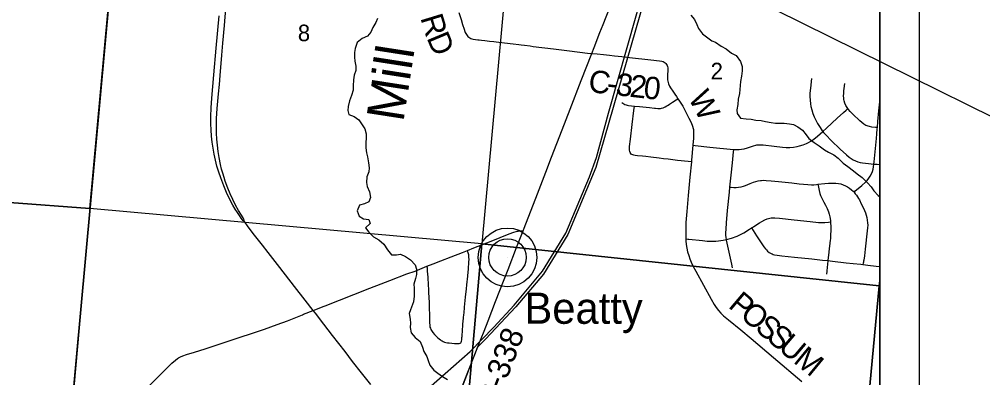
# Model space of a CAD drawing. Extents: x 0 to 34, y 0 to 22.
# Drawn here: x 6.722 to 9.161, y 14.717 to 15.624 of the extents above; entities that cross this region are included whole.
import ezdxf

# ---------------------------------------------------------------- set-up
doc = ezdxf.new("R2010")
doc.units = 0
for name, color, linetype in [('Default', 7, 'Continuous'), ('GM_X_City_Street', 7, 'Continuous'), ('GM_X_County_Road', 7, 'Continuous'), ('GM_X_County_Road_Text', 7, 'Continuous'), ('GM_X_Minor_River', 7, 'Continuous'), ('GM_X_Minor_River_Text', 7, 'Continuous'), ('GM_X_Rail_Line', 7, 'Continuous'), ('GM_X_Section', 7, 'Continuous'), ('GM_X_Section_Text', 7, 'Continuous'), ('GM_X_Township_Road', 7, 'Continuous'), ('GM_X_Township_Road_Text', 7, 'Continuous'), ('GM_X_Unincorporated', 7, 'Continuous'), ('GM_X_Unincorporated_Location', 7, 'Continuous'), ('GM_X_Unincorporated_Text', 7, 'Continuous'), ('GM_X_US_Route', 7, 'Continuous'), ('SH_Data', 7, 'Continuous'), ('SH_Text', 7, 'Continuous')]:
    doc.layers.add(name, color=color, linetype=linetype)

msp = doc.modelspace()

# ---------------------------------------------------------------- linework, layer by layer
at = {"layer": 'Default'}
for points in [[(8.9, 14.9629), (8.9, 15.9657), (7.9848, 16.0585), (7.893, 15.0559), (8.8988, 14.9496)], [(7.2235, 14.1), (7.8093, 14.1), (7.893, 15.0559), (6.9002, 15.1449), (6.8099, 14.1356), (6.8432, 14.1321)], [(7.8093, 14.1), (8.8187, 14.1), (8.8988, 14.9496), (7.893, 15.0559)], [(8.9, 14.9495), (8.9, 14.9629), (8.8988, 14.9496)], [(8.8187, 14.1), (8.9, 14.1), (8.9, 14.9495), (8.8988, 14.9496)]]:
    msp.add_lwpolyline(points, close=True, dxfattribs=at)
at = {"layer": 'GM_X_City_Street'}
for points in [[(8.9, 14.1), (8.9, 20.0308)], [(6.6663, 17.4414), (6.7406, 17.4254), (6.8171, 17.414), (6.8537, 17.4026), (6.8949, 17.4037), (6.9475, 17.3946), (6.9749, 17.3832), (6.9943, 17.3798), (7.048, 17.3741), (7.0629, 17.3706), (7.1058, 17.3541), (7.096, 17.2767), (7.0907, 17.2272), (7.0417, 16.6723), (7.0099, 16.337), (6.9769, 15.9806), (6.9764, 15.9754), (6.9745, 15.9547), (6.9742, 15.9512), (6.8413, 14.4929)], [(6.8413, 14.4929), (6.9742, 15.9512), (6.9745, 15.9547), (6.9764, 15.9754), (6.9769, 15.9806), (7.0099, 16.337), (7.0417, 16.6723), (7.0907, 17.2272), (7.096, 17.2767), (7.1058, 17.3541), (7.0629, 17.3706), (7.048, 17.3741), (6.9943, 17.3798), (6.9749, 17.3832), (6.9475, 17.3946), (6.8949, 17.4037), (6.8537, 17.4026), (6.8171, 17.414), (6.7406, 17.4254), (6.6663, 17.4414)]]:
    msp.add_lwpolyline(points, dxfattribs=at)
at = {"layer": 'GM_X_County_Road'}
msp.add_line((7.4657, 14.887), (7.4936, 14.8979), dxfattribs=at)
for points in [[(8.1707, 15.5377), (8.1766, 15.553), (8.1914, 15.5905), (8.1994, 15.6107), (8.217, 15.6538), (8.246, 15.7225), (8.2645, 15.7652), (8.2816, 15.8055)], [(7.997, 15.0885), (7.9997, 15.0955), (8.0333, 15.1823), (8.0546, 15.2374), (8.0691, 15.275), (8.0827, 15.3097), (8.096, 15.3445), (8.1163, 15.3965), (8.1444, 15.4689), (8.1707, 15.5377)], [(8.1707, 15.5377), (8.1845, 15.5364), (8.2007, 15.5346), (8.2081, 15.5338), (8.2157, 15.533), (8.2281, 15.5317), (8.2466, 15.5297), (8.2665, 15.5275), (8.3206, 15.5213), (8.3425, 15.5188), (8.3485, 15.5178), (8.3514, 15.517), (8.3541, 15.5158), (8.3565, 15.5142), (8.3587, 15.5122), (8.3604, 15.5098), (8.3618, 15.5072), (8.3627, 15.5044), (8.3632, 15.5014), (8.3633, 15.4984), (8.3632, 15.4923), (8.3629, 15.4861), (8.3625, 15.4768), (8.3627, 15.4705), (8.3631, 15.4673), (8.3639, 15.4639), (8.3651, 15.4605), (8.3678, 15.4552), (8.3705, 15.4505), (8.3758, 15.4423), (8.3811, 15.4346), (8.3853, 15.4284), (8.389, 15.4227)], [(8.389, 15.4227), (8.3931, 15.4169), (8.3963, 15.4118), (8.401, 15.4039), (8.4084, 15.3903), (8.417, 15.3738), (8.4222, 15.3626), (8.4257, 15.354), (8.4274, 15.3481), (8.428, 15.3451), (8.4286, 15.339), (8.4287, 15.3329), (8.4282, 15.3236), (8.4266, 15.3055)], [(8.4266, 15.3055), (8.4234, 15.2679), (8.423, 15.2631)], [(8.423, 15.2631), (8.4194, 15.2246), (8.4148, 15.1782), (8.4113, 15.1379), (8.4094, 15.11), (8.4086, 15.0914), (8.4086, 15.0758), (8.4089, 15.0683)], [(7.7537, 14.999), (7.7693, 15.0052), (7.7887, 15.0128), (7.8148, 15.0228), (7.8437, 15.0341), (7.856, 15.0389), (7.8726, 15.0455), (7.9159, 15.0626), (7.9621, 15.0811), (7.9737, 15.0855), (7.9795, 15.0872), (7.9824, 15.0878), (7.9846, 15.0883), (7.9867, 15.0885), (7.9892, 15.0885), (7.9949, 15.0885), (7.997, 15.0885)], [(7.7781, 14.5434), (7.7795, 14.5452), (7.7848, 14.5528), (7.7895, 14.5608), (7.7937, 14.569), (7.7987, 14.5803), (7.8089, 14.6063), (7.8301, 14.6601), (7.8465, 14.702), (7.8702, 14.7628), (7.8835, 14.7975), (7.8982, 14.8352), (7.9084, 14.8612), (7.9276, 14.9103), (7.9492, 14.9652), (7.9593, 14.9913), (7.9806, 15.0463), (7.997, 15.0885)], [(8.4089, 15.0683), (8.409, 15.0633), (8.4099, 15.054), (8.4114, 15.0447), (8.4136, 15.0356), (8.4163, 15.0266), (8.4195, 15.0178), (8.4229, 15.0091), (8.4268, 15.0006), (8.4339, 14.9867), (8.4534, 14.9513), (8.4729, 14.9159), (8.4808, 14.9024), (8.4859, 14.8946), (8.4916, 14.8871), (8.4979, 14.8802), (8.5047, 14.8737), (8.5166, 14.8635), (8.548, 14.8381), (8.5745, 14.8165), (8.6313, 14.7682), (8.7025, 14.7079)], [(7.4936, 14.8979), (7.4964, 14.899), (7.5687, 14.9273), (7.6091, 14.9435), (7.6379, 14.955), (7.6597, 14.9633), (7.7027, 14.9796), (7.7239, 14.987), (7.7417, 14.9943), (7.7537, 14.999)], [(7.4386, 14.8764), (7.4414, 14.8775), (7.4657, 14.887)], [(6.8408, 14.4917), (6.8415, 14.4924), (6.8505, 14.5014), (6.9283, 14.5774), (6.9993, 14.6471), (7.0594, 14.7056), (7.0838, 14.7296), (7.1082, 14.7535), (7.1173, 14.7619), (7.1221, 14.7656), (7.1247, 14.7672), (7.1302, 14.77), (7.1359, 14.7723), (7.1446, 14.7755), (7.1653, 14.7821), (7.192, 14.7905), (7.248, 14.8091), (7.3424, 14.8403), (7.3747, 14.8516), (7.4009, 14.8614), (7.4386, 14.8764)]]:
    msp.add_lwpolyline(points, dxfattribs=at)
at = {"layer": 'GM_X_Minor_River'}
for points in [[(8.4217, 15.6345), (8.4307, 15.6231), (8.4366, 15.6105), (8.4407, 15.601), (8.4516, 15.5869), (8.4648, 15.577), (8.4745, 15.5693), (8.4844, 15.5658), (8.4983, 15.5562), (8.5107, 15.5497), (8.5246, 15.5382), (8.5367, 15.5321), (8.5475, 15.5176), (8.5512, 15.5047), (8.5519, 15.4937), (8.5499, 15.48), (8.5472, 15.4668), (8.5467, 15.4562), (8.5455, 15.4463), (8.545, 15.4365), (8.5419, 15.4217), (8.5403, 15.4088), (8.5383, 15.3948), (8.5386, 15.3853), (8.5476, 15.3739), (8.5616, 15.3719), (8.5744, 15.3714), (8.5862, 15.369), (8.6001, 15.3678), (8.6107, 15.3654), (8.6251, 15.3627), (8.636, 15.3615), (8.6474, 15.361), (8.6583, 15.3609), (8.6712, 15.3597), (8.6818, 15.3577), (8.6923, 15.3523), (8.704, 15.3439), (8.7134, 15.3317), (8.7205, 15.3221), (8.734, 15.3122), (8.7464, 15.3038), (8.76, 15.2938), (8.7698, 15.288), (8.7833, 15.2807), (8.7946, 15.2727), (8.807, 15.2601), (8.8187, 15.2516), (8.8334, 15.2409), (8.8431, 15.2333), (8.8555, 15.2241), (8.8691, 15.2099), (8.8781, 15.2), (8.8848, 15.1901), (8.8961, 15.1783), (8.9, 15.1748)], [(7.6287, 15.626), (7.6245, 15.6162), (7.6168, 15.6029), (7.6118, 15.5916), (7.6031, 15.5811), (7.5894, 15.5751), (7.5772, 15.5657), (7.5722, 15.5502), (7.5706, 15.5404), (7.5701, 15.5278), (7.5708, 15.518), (7.5737, 15.5051), (7.574, 15.4941), (7.5698, 15.4824), (7.5674, 15.4706), (7.5673, 15.4558), (7.5669, 15.4448), (7.563, 15.4308), (7.558, 15.4176), (7.5544, 15.4032), (7.5532, 15.3934), (7.5562, 15.3835), (7.5698, 15.3781), (7.581, 15.3697), (7.5897, 15.3571), (7.5964, 15.3472), (7.6001, 15.3343), (7.5996, 15.3244), (7.5991, 15.3115), (7.5987, 15.299), (7.6008, 15.2861), (7.603, 15.2759), (7.6056, 15.2611), (7.6078, 15.2482), (7.6069, 15.2383), (7.6019, 15.2258), (7.6003, 15.2114), (7.6021, 15.2008), (7.6081, 15.1871)], [(7.6081, 15.1871), (7.6106, 15.1734), (7.6067, 15.1621), (7.5953, 15.1569), (7.5832, 15.1539), (7.5767, 15.1392), (7.5819, 15.1259), (7.5932, 15.119), (7.6068, 15.1174), (7.6097, 15.1075), (7.5983, 15.0962), (7.6062, 15.0855), (7.6182, 15.0737), (7.6317, 15.0664), (7.6445, 15.0549), (7.6535, 15.0404), (7.664, 15.0278), (7.6768, 15.0277), (7.6863, 15.0296), (7.6991, 15.0238), (7.7123, 15.0157), (7.7239, 15.0028), (7.7276, 14.9921), (7.7272, 14.9785), (7.7248, 14.9679), (7.7205, 14.9535), (7.7212, 14.944), (7.7215, 14.9326), (7.7211, 14.9232), (7.7195, 14.9088), (7.7117, 14.8891), (7.709, 14.8793), (7.7108, 14.8656), (7.7122, 14.855), (7.711, 14.8444), (7.714, 14.8307), (7.7237, 14.8189), (7.7365, 14.8089), (7.7424, 14.7945), (7.7454, 14.7838), (7.7532, 14.7705), (7.7569, 14.7606), (7.761, 14.7492), (7.7711, 14.7363), (7.7813, 14.7286), (7.7933, 14.7202), (7.8054, 14.7125)]]:
    msp.add_lwpolyline(points, dxfattribs=at)
at = {"layer": 'GM_X_Rail_Line'}
for points in [[(7.2798, 14.1), (7.3804, 14.2899), (7.4399, 14.3809), (7.5029, 14.451), (7.5671, 14.514), (7.6729, 14.6161), (7.8627, 14.7836), (7.9234, 14.8447), (7.9746, 14.9008), (8.0463, 14.9864), (8.1054, 15.083), (8.1652, 15.2252), (8.1826, 15.274), (8.2135, 15.3861), (8.2835, 15.6324), (8.3606, 15.9006), (8.4204, 16.0285), (8.4785, 16.1527), (8.5411, 16.2834), (8.5955, 16.4012), (8.7466, 16.719), (8.8431, 16.9243), (8.9, 17.0477)], [(8.6715, 16.5448), (8.4316, 16.0366), (8.3713, 15.9072), (8.1815, 15.2486), (8.1107, 15.0795), (8.0486, 14.9789), (7.9789, 14.8968), (7.9015, 14.815), (7.882, 14.794), (7.8474, 14.7064), (7.8234, 14.6409), (7.725, 14.3971), (7.6108, 14.1)]]:
    msp.add_lwpolyline(points, dxfattribs=at)
at = {"layer": 'GM_X_Section'}
for points in [[(5.9902, 16.2292), (6.992, 16.1486), (6.9002, 15.1449), (5.8825, 15.2209)], [(6.992, 16.1486), (7.9848, 16.0585), (7.893, 15.0559), (6.9002, 15.1449)], [(5.8825, 15.2209), (6.9002, 15.1449), (6.8099, 14.1356), (5.8205, 14.2252), (5.7982, 14.227)]]:
    msp.add_lwpolyline(points, close=True, dxfattribs=at)
at = {"layer": 'GM_X_Township_Road'}
for points in [[(7.8348, 15.6409), (7.8403, 15.6231), (7.844, 15.6112), (7.8475, 15.5993), (7.8495, 15.5935), (7.8507, 15.5906), (7.852, 15.5879), (7.8535, 15.5853), (7.8553, 15.5829), (7.8573, 15.5807), (7.8597, 15.5787), (7.8621, 15.5771), (7.8648, 15.5757), (7.8676, 15.5747), (7.8705, 15.5739), (7.8765, 15.5728), (7.8827, 15.5721), (7.8858, 15.5718), (7.892, 15.5711), (7.8999, 15.5702), (7.9118, 15.5689), (7.9226, 15.5677), (7.9293, 15.5669), (7.9502, 15.5646), (7.9715, 15.5621), (7.9866, 15.5602), (7.9921, 15.5595), (8.001, 15.5584), (8.0146, 15.5567), (8.0229, 15.5556), (8.074, 15.5492), (8.1141, 15.5443), (8.1604, 15.5387), (8.1707, 15.5377)], [(8.7271, 15.4745), (8.7242, 15.4499), (8.7233, 15.4375), (8.7232, 15.4283), (8.7236, 15.419), (8.7246, 15.4097), (8.7257, 15.4036), (8.728, 15.3947), (8.7308, 15.3858), (8.7339, 15.3771), (8.7377, 15.3686), (8.7421, 15.3604), (8.7487, 15.3499), (8.7539, 15.3422), (8.7557, 15.34)], [(8.8193, 15.398), (8.8173, 15.4008), (8.8143, 15.4062), (8.8118, 15.412), (8.81, 15.418), (8.8093, 15.421), (8.8088, 15.4241), (8.8085, 15.4304), (8.8086, 15.4366), (8.8091, 15.4429), (8.8099, 15.449), (8.8119, 15.4614)], [(8.2468, 15.4138), (8.2493, 15.4118), (8.2519, 15.41), (8.2547, 15.4085), (8.2576, 15.4075), (8.2607, 15.4067), (8.2638, 15.4062), (8.2791, 15.4045)], [(8.2791, 15.4045), (8.2919, 15.4033), (8.3172, 15.4005), (8.3294, 15.3992), (8.3325, 15.3989), (8.3382, 15.3983), (8.3415, 15.3984), (8.3446, 15.3987), (8.3476, 15.3992), (8.3514, 15.4004), (8.3564, 15.4026), (8.361, 15.4051), (8.3641, 15.4069), (8.3677, 15.4092), (8.3756, 15.414), (8.3845, 15.4199), (8.389, 15.4227)], [(8.894, 15.3499), (8.8953, 15.365), (8.8979, 15.3925), (8.8993, 15.4079), (8.9, 15.4157)], [(8.423, 15.2631), (8.4152, 15.2639), (8.3876, 15.267), (8.3759, 15.2685), (8.3646, 15.2698), (8.3527, 15.2713), (8.3415, 15.2725), (8.3201, 15.2752), (8.3078, 15.2765), (8.299, 15.2776), (8.2867, 15.2787), (8.2806, 15.2795), (8.2775, 15.28), (8.2745, 15.2807), (8.2718, 15.2821), (8.2696, 15.2842), (8.2679, 15.2868), (8.2669, 15.2897), (8.2664, 15.2928), (8.2662, 15.2959), (8.2667, 15.302), (8.2688, 15.3205), (8.2733, 15.3576), (8.2776, 15.3936), (8.2791, 15.4045)], [(8.7557, 15.34), (8.7651, 15.3488), (8.792, 15.3735), (8.8078, 15.3879), (8.8147, 15.3939), (8.8193, 15.398)], [(8.894, 15.3499), (8.8891, 15.3504), (8.8798, 15.3514), (8.8736, 15.3526), (8.8706, 15.3534), (8.8677, 15.3545), (8.8648, 15.3557), (8.862, 15.3571), (8.8593, 15.3587), (8.8543, 15.3626), (8.8497, 15.3667), (8.8316, 15.3841), (8.825, 15.3908), (8.8209, 15.3956), (8.8193, 15.398)], [(8.8851, 15.2578), (8.8858, 15.2631), (8.8889, 15.2972), (8.8913, 15.322), (8.8925, 15.3344), (8.8937, 15.3467), (8.894, 15.3499)], [(8.5294, 15.2949), (8.5317, 15.2947), (8.5379, 15.2943), (8.5441, 15.2945), (8.5501, 15.2952), (8.5563, 15.2966), (8.5652, 15.2992), (8.58, 15.304), (8.586, 15.3054), (8.589, 15.306), (8.5921, 15.3063), (8.5983, 15.3064), (8.6045, 15.306), (8.6322, 15.3028), (8.6538, 15.3004), (8.6631, 15.2999), (8.6724, 15.3), (8.6816, 15.3008), (8.6908, 15.3022), (8.6969, 15.3036), (8.7057, 15.3064), (8.7144, 15.3099), (8.7199, 15.3126), (8.7253, 15.3156), (8.733, 15.3209), (8.7427, 15.3287), (8.7557, 15.34)], [(8.7557, 15.34), (8.7577, 15.3374), (8.764, 15.3305), (8.7771, 15.3173), (8.7994, 15.2958), (8.8154, 15.2811), (8.8226, 15.2752), (8.8277, 15.2717), (8.833, 15.2685), (8.8385, 15.2657), (8.8443, 15.2636), (8.8503, 15.2619), (8.8564, 15.2608), (8.8718, 15.259), (8.8851, 15.2578)], [(8.4266, 15.3055), (8.433, 15.3048), (8.47, 15.3008), (8.5294, 15.2949)], [(8.5294, 15.2949), (8.5288, 15.2889), (8.526, 15.2609), (8.523, 15.23), (8.5197, 15.1993)], [(8.8347, 15.1866), (8.8371, 15.189), (8.8543, 15.2035), (8.8635, 15.2121), (8.8678, 15.2163), (8.8725, 15.2221), (8.876, 15.2273), (8.8789, 15.2328), (8.8812, 15.2386), (8.8829, 15.2446), (8.8841, 15.2507), (8.8851, 15.2578)], [(8.8851, 15.2578), (8.8933, 15.2571), (8.9, 15.2564)], [(8.5197, 15.1993), (8.5184, 15.1865), (8.514, 15.14), (8.5111, 15.1088), (8.51, 15.0933), (8.5094, 15.084), (8.5094, 15.0778), (8.5099, 15.0716), (8.5107, 15.0667)], [(8.5197, 15.1993), (8.524, 15.199), (8.5302, 15.1986), (8.5364, 15.1987), (8.5426, 15.1992), (8.5487, 15.2003), (8.5547, 15.2018), (8.5604, 15.2037), (8.5718, 15.2084), (8.5804, 15.212), (8.5864, 15.214), (8.5924, 15.2154), (8.598, 15.2163), (8.6006, 15.2165), (8.6063, 15.2167), (8.6124, 15.2165), (8.6248, 15.2156), (8.6434, 15.2137), (8.6774, 15.2102), (8.696, 15.2081), (8.7177, 15.2059), (8.727, 15.2054), (8.7332, 15.2055), (8.7394, 15.2061), (8.7431, 15.2066)], [(8.7431, 15.2066), (8.761, 15.2089), (8.7703, 15.2096), (8.7796, 15.2097), (8.7889, 15.2094), (8.7951, 15.2086), (8.8012, 15.2073), (8.8071, 15.2053), (8.8128, 15.2029), (8.8183, 15.1999), (8.8234, 15.1965), (8.8282, 15.1925), (8.8324, 15.1888), (8.8347, 15.1866)], [(8.7431, 15.2066), (8.7445, 15.1996), (8.7463, 15.1904), (8.7483, 15.1835), (8.7502, 15.1784), (8.7525, 15.1727), (8.7548, 15.1678), (8.7581, 15.1617), (8.7627, 15.1537), (8.7668, 15.1452), (8.7703, 15.1366), (8.7722, 15.1306), (8.7735, 15.1245), (8.7749, 15.1152), (8.7753, 15.1114)], [(8.8347, 15.1866), (8.8376, 15.1828), (8.8407, 15.1786), (8.8436, 15.1745), (8.8463, 15.1703), (8.8482, 15.167), (8.853, 15.1571), (8.8584, 15.1459), (8.8635, 15.1345), (8.8656, 15.1286), (8.8671, 15.1223), (8.8683, 15.1159), (8.8691, 15.1088), (8.8693, 15.1031), (8.8691, 15.0964), (8.8681, 15.0885), (8.8626, 15.0425), (8.8609, 15.0257), (8.8594, 15.0145), (8.859, 15.0118), (8.8585, 15.0093), (8.8579, 15.0068), (8.857, 15.0034)], [(8.5756, 15.096), (8.5806, 15.0991), (8.5863, 15.1028), (8.5956, 15.1087), (8.6018, 15.1127), (8.6094, 15.117), (8.6145, 15.1192), (8.6186, 15.1202), (8.6216, 15.1209), (8.6246, 15.1214), (8.6277, 15.1217), (8.6339, 15.1217), (8.6463, 15.1206), (8.6833, 15.1168), (8.7234, 15.1122), (8.745, 15.1099), (8.7536, 15.1098), (8.7609, 15.1099), (8.7702, 15.1109), (8.7753, 15.1114)], [(8.7753, 15.1114), (8.7756, 15.109), (8.7763, 15.0997), (8.7764, 15.0934), (8.7754, 15.0747), (8.7749, 15.0685), (8.7746, 15.0654), (8.7729, 15.05), (8.7722, 15.0438), (8.7713, 15.0346), (8.7684, 15.0133)], [(8.5107, 15.0667), (8.5123, 15.067), (8.5243, 15.0704), (8.5389, 15.0755), (8.5474, 15.0793), (8.5556, 15.0836), (8.5702, 15.0926), (8.5756, 15.096)], [(8.5756, 15.096), (8.5795, 15.0899), (8.5882, 15.0765), (8.6013, 15.0557), (8.6065, 15.048), (8.6103, 15.0433), (8.6129, 15.0403), (8.616, 15.0373), (8.6197, 15.0342), (8.6218, 15.0327), (8.6246, 15.0312), (8.6273, 15.0303), (8.6305, 15.0292), (8.6335, 15.0284), (8.6404, 15.0273), (8.6518, 15.0258), (8.6843, 15.0224), (8.7279, 15.0178), (8.7553, 15.0147), (8.7684, 15.0133)], [(8.4089, 15.0683), (8.4138, 15.0679), (8.4169, 15.0676), (8.4508, 15.0639), (8.4632, 15.0628), (8.4755, 15.0623), (8.4846, 15.0624), (8.4919, 15.0631), (8.5032, 15.065), (8.5107, 15.0667)], [(8.5107, 15.0667), (8.5109, 15.0654), (8.5245, 15.0045), (8.5265, 14.9954)], [(7.7537, 14.999), (7.7541, 14.9937), (7.7545, 14.9875), (7.7553, 14.9782), (7.7558, 14.972), (7.7567, 14.9505), (7.7573, 14.9417), (7.7577, 14.9365), (7.758, 14.9307), (7.7585, 14.9216), (7.7591, 14.9061), (7.7595, 14.8936), (7.76, 14.875), (7.7603, 14.8656), (7.7603, 14.8555), (7.7606, 14.8512), (7.7607, 14.8482), (7.7613, 14.8451), (7.7623, 14.8422), (7.7636, 14.8393), (7.7651, 14.8366), (7.7667, 14.834), (7.7685, 14.8315), (7.7725, 14.8267), (7.7767, 14.8222), (7.7813, 14.818), (7.7877, 14.813), (7.7897, 14.8115), (7.7921, 14.8101), (7.7951, 14.8085), (7.7979, 14.8074), (7.8012, 14.8064), (7.8058, 14.8057), (7.8103, 14.805), (7.823, 14.8038), (7.8261, 14.8035), (7.8292, 14.8034), (7.8324, 14.8034), (7.8354, 14.8039), (7.838, 14.8049), (7.8391, 14.8057), (7.8401, 14.807), (7.8412, 14.8097), (7.8417, 14.8128), (7.8421, 14.8158), (7.8422, 14.8186), (7.8425, 14.8218), (7.8427, 14.826), (7.8434, 14.8343), (7.8449, 14.8527), (7.8464, 14.868), (7.8466, 14.8708), (7.8469, 14.8742), (7.8471, 14.8773), (7.8475, 14.8804), (7.8489, 14.8959), (7.8514, 14.9207), (7.8538, 14.9424), (7.8548, 14.9517), (7.857, 14.9739), (7.8581, 14.9849), (7.8586, 14.9909), (7.8591, 14.9977), (7.8594, 15.0042), (7.8599, 15.0104), (7.8603, 15.0166), (7.8601, 15.0224), (7.8593, 15.0277), (7.857, 15.0356), (7.856, 15.0389)], [(8.7684, 15.0133), (8.7674, 15.0039), (8.7667, 14.9971), (8.7656, 14.9869), (8.7647, 14.9788)], [(8.7684, 15.0133), (8.7806, 15.0118), (8.8149, 15.0082), (8.8323, 15.0062), (8.8517, 15.004), (8.857, 15.0034)], [(8.857, 15.0034), (8.8764, 15.0012), (8.898, 14.9989)]]:
    msp.add_lwpolyline(points, dxfattribs=at)
at = {"layer": 'GM_X_Unincorporated'}
for radius in [0.0744, 0.0472]:
    msp.add_circle((7.9576, 15.0215), radius, dxfattribs=at)
at = {"layer": 'GM_X_Unincorporated_Location'}
msp.add_line((7.9576, 15.0215), (7.9576, 15.0215), dxfattribs=at)
at = {"layer": 'GM_X_US_Route'}
for points in [[(7.2282, 15.4592), (7.23, 15.4817), (7.2347, 15.533), (7.2373, 15.5634), (7.2414, 15.6083), (7.2433, 15.6301), (7.2552, 15.7635), (7.259, 15.8044), (7.2619, 15.8371), (7.264, 15.8595), (7.2651, 15.8703), (7.2713, 15.9402), (7.2722, 15.9493), (7.2739, 15.966)], [(7.2919, 15.112), (7.2887, 15.1144), (7.2861, 15.1172), (7.2833, 15.1208), (7.279, 15.1272), (7.2738, 15.1351), (7.268, 15.144), (7.2624, 15.1535), (7.2531, 15.1715), (7.2464, 15.1855), (7.2392, 15.2026), (7.2315, 15.2229), (7.2265, 15.2376), (7.2221, 15.2524), (7.2182, 15.2674), (7.2149, 15.2826), (7.2121, 15.2978), (7.2099, 15.3131), (7.2082, 15.3285), (7.2071, 15.344), (7.2066, 15.3594), (7.2066, 15.378), (7.2073, 15.3997), (7.2089, 15.4245), (7.214, 15.4833), (7.2202, 15.5513), (7.2274, 15.6331)], [(7.2919, 15.112), (7.2909, 15.1154), (7.2902, 15.1175), (7.2881, 15.1217), (7.2764, 15.1402), (7.2689, 15.1538), (7.262, 15.1678), (7.2558, 15.1821), (7.25, 15.1965), (7.2432, 15.2144), (7.2401, 15.2234), (7.237, 15.2343), (7.234, 15.2448), (7.231, 15.2568), (7.2277, 15.2741), (7.2251, 15.2897), (7.2231, 15.3058), (7.222, 15.3207), (7.2213, 15.3359), (7.2208, 15.354), (7.2213, 15.3727), (7.2228, 15.398), (7.2263, 15.4357), (7.2282, 15.4592)], [(7.4657, 14.887), (7.4453, 14.9133), (7.4181, 14.948), (7.3956, 14.977), (7.3752, 15.0033), (7.3514, 15.034), (7.3372, 15.0524), (7.3175, 15.0781), (7.3014, 15.099), (7.2919, 15.112)], [(7.6115, 14.6995), (7.588, 14.7295), (7.5656, 14.7585), (7.5465, 14.7831), (7.5306, 14.8035), (7.5145, 14.8242), (7.4924, 14.8524), (7.4712, 14.88), (7.4657, 14.887)]]:
    msp.add_lwpolyline(points, dxfattribs=at)
at = {"layer": 'SH_Data'}
for p, q in [((9, 21), (9, 14)), ((8.9, 20.9), (8.9, 14.1))]:
    msp.add_line(p, q, dxfattribs=at)
at = {"layer": 'SH_Text'}
msp.add_lwpolyline([(9.3277, 15.6016), (4.1983, 17.8389), (9.3277, 15.3062)], close=True, dxfattribs=at)

# ---------------------------------------------------------------- texts
at = {"layer": 'GM_X_County_Road_Text'}
for s, height, rotation, p in [('C', 0.0568, 353.2913, (8.1605, 15.4405)), ('3', 0.0568, 353.3432, (8.2301, 15.4323)), ('2', 0.0568, 353.4658, (8.265, 15.4283)), ('0', 0.0568, 353.8878, (8.3002, 15.4242)), ('-', 0.0568, 353.3006, (8.2069, 15.4351)), ('W', 0.0568, 297.3396, (8.4142, 15.4261)), ('P', 0.0568, 319.7108, (8.5141, 14.8965)), ('O', 0.0568, 319.7114, (8.5434, 14.8717)), ('S', 0.0568, 319.709, (8.5815, 14.8394)), ('C-338', 0.05682, 68.9618, (7.927, 14.636)), ('S', 0.0568, 319.7098, (8.6107, 14.8146)), ('U', 0.0568, 319.714, (8.64, 14.7898)), ('M', 0.0568, 320.5724, (8.6788, 14.7569))]:
    msp.add_text(s, height=height, rotation=rotation, dxfattribs=at).set_placement(p)
at = {"layer": 'GM_X_Minor_River_Text'}
msp.add_text('Mill', height=0.09467, rotation=81.1767, dxfattribs=at).set_placement((7.6938, 15.362))
at = {"layer": 'GM_X_Section_Text'}
for s, p in [('8', (7.4268, 15.5686)), ('2', (8.4718, 15.4722))]:
    msp.add_text(s, height=0.0419, rotation=0, dxfattribs=at).set_placement(p)
at = {"layer": 'GM_X_Township_Road_Text'}
for s, rotation, p in [('R', 286.997, (7.7366, 15.6277)), ('D', 292.6768, (7.7523, 15.5773))]:
    msp.add_text(s, height=0.0568, rotation=rotation, dxfattribs=at).set_placement(p)
at = {"layer": 'GM_X_Unincorporated_Text'}
msp.add_text('Beatty', height=0.07898, rotation=0, dxfattribs=at).set_placement((8.0005, 14.8535))

doc.saveas('drawing.dxf')
